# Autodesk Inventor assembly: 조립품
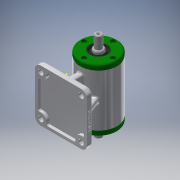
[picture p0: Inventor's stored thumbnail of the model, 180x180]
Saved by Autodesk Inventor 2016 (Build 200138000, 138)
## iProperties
Created: 2019-06
Part Number: 조립품
Material: 일반
Document SubType Name: Assembly
Designer: 605-12
Author: 605-12
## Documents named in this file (7)
- C:\Users\605-12\Desktop\490604V1020\조립품.iam
- C:\Users\605-12\Desktop\490604V1020\부품1.ipt
- C:\Users\605-12\Desktop\490604V1020\커버.ipt
- C:\Users\605-12\Desktop\490604V1020\베어링 6203.ipt
- C:\Users\605-12\Desktop\490604V1020\오일 실 17 30 5.ipt
- C:\Users\605-12\Desktop\490604V1020\축.ipt
- C:\Users\605-12\Desktop\490604V1020\키 4x4x12.ipt
